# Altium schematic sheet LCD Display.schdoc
size 297 x 209 mm; Symbol: Drawing-Symbol_A4; @Project Name: Hưhwwuey; @Page Count: 4; @Update Date: 2026-10-18; @Create Date: 2026-10-18; @Schematic Name: Schematic1; @Page No: 4; @Page Name: P1; Company: EasyEDA.com; Version: V1.0; Page Size: A4; Device: Drawing-Symbol_A4; @Create Time: 08:51:09; @Update Time: 08:51:09; Border: 1; Width: 1170; Height: 825; Region Start: 1; X Region Count: 6; Y Region Count: 4; Blade Width: 10; Title Block Position: 3; @Board Name: Board1
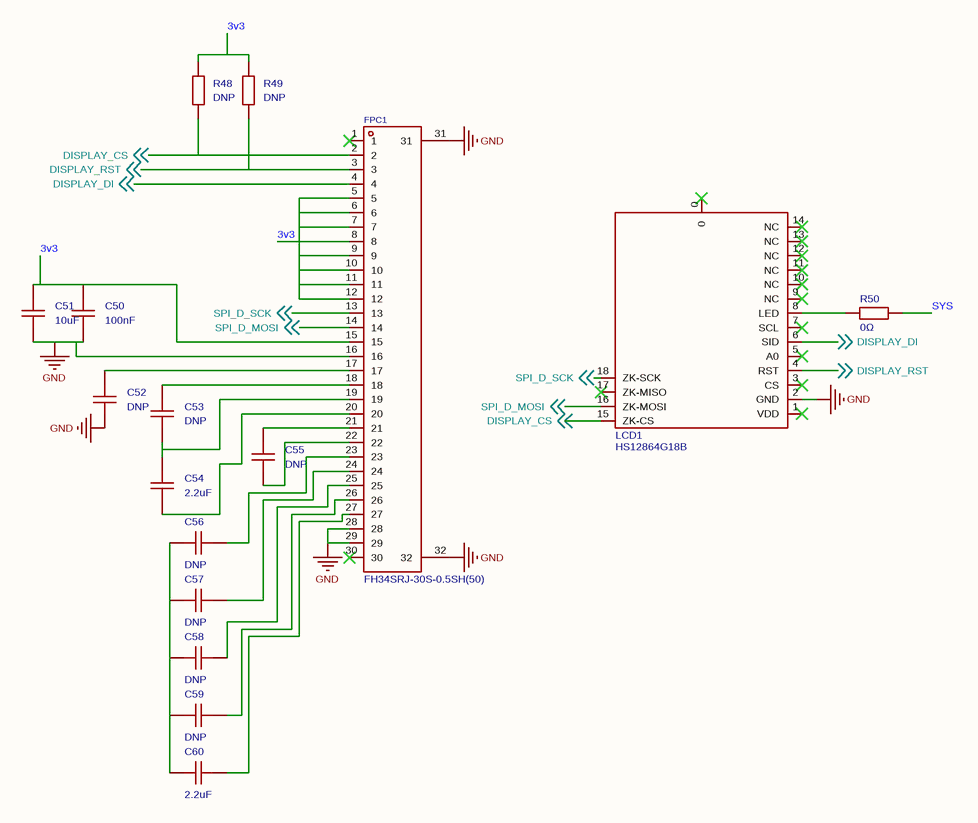
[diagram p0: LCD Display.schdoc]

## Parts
C50  100nF  [C0402]
C51  10uF  [C0603]
C52  DNP  [C0402]
C53  DNP  [C0402]
C54  2.2uF  [C0402]
C55  DNP  [C0402]
C56  DNP  [C0402]
C57  DNP  [C0402]
C58  DNP  [C0402]
C59  DNP  [C0402]
C60  2.2uF  [C0402]
FPC1  FH34SRJ-30S-0.5SH(50)  [FFC-SMD_30P-P0.50_FH34SRJ-30S-0.5SH]
LCD1  HS12864G18B  [COMM-TH_HS12864G18B]
R48  DNP  [R0402]
R49  DNP  [R0402]
R50  0Ω  [R0402]

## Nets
GND: C50.2 C51.1 C52.2 FPC1.16 FPC1.28 FPC1.29 FPC1.31 FPC1.32 LCD1.2(GND)
3v3: C50.1 C51.2 FPC1.5 FPC1.6 FPC1.7 FPC1.8 FPC1.9 FPC1.10 FPC1.11 FPC1.12 FPC1.15 R48.2 R49.2
DISPLAY_CS: FPC1.2 LCD1.15(ZK-CS) R48.1 ; off-sheet DISPLAY_CS
DISPLAY_DI: FPC1.4 LCD1.6(SID) ; off-sheet DISPLAY_DI
DISPLAY_RST: FPC1.3 LCD1.4(RST) R49.1 ; off-sheet DISPLAY_RST
SPI_D_MOSI: FPC1.14 LCD1.16(ZK-MOSI) ; off-sheet SPI_D_MOSI
SPI_D_SCK: FPC1.13 LCD1.18(ZK-SCK) ; off-sheet SPI_D_SCK
SYS: R50.1
NetC52_1: C52.1 FPC1.17
NetC53_1: C53.1 FPC1.18
NetC53_2: C53.2 C54.2 FPC1.19
NetC54_1: C54.1 FPC1.20
NetC55_1: C55.1 FPC1.21
NetC55_2: C55.2 FPC1.22
NetC56_1: C56.1 C57.1 C58.1 C59.1 C60.2
NetC56_2: C56.2 FPC1.23
NetC57_2: C57.2 FPC1.24
NetC58_2: C58.2 FPC1.25
NetC59_2: C59.2 FPC1.26
NetC60_1: C60.1 FPC1.27
NetLCD1_8: LCD1.8(LED) R50.2

Not connected (* = marked no-connect by the designer): FPC1 1* 30*; LCD1 0* 1(VDD)* 3(CS)* 5(A0)* 7(SCL)* 9(NC)* 10(NC)* 11(NC)* 12(NC)* 13(NC)* 14(NC)* 17(ZK-MISO)*

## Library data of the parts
C50 = CAP_0402: Symbol: CAP_OLD; 3D Model: b7d13df3e9464d7a99d0651d1a5b4d570819f05c4eef4c71ace90d822a990e87; 3D Model Transform: 39.37,19.685,0,0,0,0,0,0,0; ConvertToPcb: yes; ModelName: C0402_L1.0-W0.5-H0.5
C51 = CL10A106KP8NNNC: Capacitance:10uF Tolerance:±10% Tolerance:±10% Voltage Rating:10V Temperature Coefficient:X5R; Manufacturer: SAMSUNG(三星); AddInBom: yes; ModelId: 624118aa3cc7497086c383c2d72e08520819f05c4eef4c71ace90d822a990e87; ModelName: C0603_L1.6-W0.8-H0.8; ModelTransform: 62.992,31.496,0,0,0,0,0,0,0; Tolerance: ±10%; Voltage Rating: 10V; Temperature Coefficient: X5R
C52 = CAP_0402: Symbol: CAP_OLD; 3D Model: b7d13df3e9464d7a99d0651d1a5b4d570819f05c4eef4c71ace90d822a990e87; 3D Model Transform: 39.37,19.685,0,0,0,0,0,0,0; Add into BOM: no; ConvertToPcb: yes; ModelName: C0402_L1.0-W0.5-H0.5
C53 C55-C59 = CAP_0402: Symbol: CAP_OLD; Add into BOM: no; 3D Model: b7d13df3e9464d7a99d0651d1a5b4d570819f05c4eef4c71ace90d822a990e87; 3D Model Transform: 39.37,19.685,0,0,0,0,0,0,0; ConvertToPcb: yes; ModelName: C0402_L1.0-W0.5-H0.5
C54 C60 = CL05A225MQ5NSNC: Capacitance:2.2uF Tolerance:±20% Tolerance:±20% Voltage Rating:6.3V Temperature Coefficient:X5R; Manufacturer: SAMSUNG(三星); AddInBom: yes; ModelId: b7d13df3e9464d7a99d0651d1a5b4d570819f05c4eef4c71ace90d822a990e87; ModelName: C0402_L1.0-W0.5-H0.5; ModelTransform: 39.37,19.685,0,0,0,0,0,0,0; Tolerance: ±20%; Voltage Rating: 6.3V; Temperature Coefficient: X5R
FPC1 = FH34SRJ-30S-0.5SH(50): Locking Feature:Flip-top (front insert,rear flip) Contact Type:Double-Sided Contacts, Top and Bottom Entry Number of Contacts:30P Pitch:0.5mm Mounting Type:Surface Mount, Right Angle FFC, FCB Thickness:0.3mm FFC, FCB Thickness:0.3mm Height Above Board:1mm; Manufacturer: HRS(广濑); AddInBom: yes; ModelId: 0c4f2e658d844e86a41377a272355f670819f05c4eef4c71ace90d822a990e87; ModelTransform: 669.29,149.606,0,0,0,0,0.004,5.906,0; Number of Contacts: 30P; Pitch: 0.5mm; FFC, FCB Thickness: 0.3mm; Rated Voltage (Max): 50V; Current Rating (Max): 500mA; FPC/FFC Lock: Without buckle; Forward Foot / Back Foot: No polarity
LCD1 = HS12864G18B: Main Control Chip:ST7567 Size:3; Manufacturer: HS(汉昇); AddInBom: yes; ModelId: 82f3b8a5681848b091cb1c7b6c8d4e640819f05c4eef4c71ace90d822a990e87; ModelTransform: 3385.82,1968.5,0,0,0,0,-19.488,0,-185.039; Main Control Chip: ST7567
R48 = Res_0402: Symbol: Res; 3D Model: efdecb7dae4442949d28eecaf748420f0819f05c4eef4c71ace90d822a990e87; 3D Model Transform: 39.37,19.685,0,0,0,0,0,0,0; Add into BOM: no; ConvertToPcb: yes; ModelName: R0402_L1.0-W0.5-H0.4
R49 = Res_0402: Symbol: Res; Add into BOM: no; 3D Model: efdecb7dae4442949d28eecaf748420f0819f05c4eef4c71ace90d822a990e87; 3D Model Transform: 39.37,19.685,0,0,0,0,0,0,0; ConvertToPcb: yes; ModelName: R0402_L1.0-W0.5-H0.4
R50 = MR04X000PTL: Type:Thick Film Resistors Resistance: Power(Watts): Overload Voltage (Max): Temperature Coefficient:-200ppm/℃~+400ppm/℃ Temperature Coefficient:-200ppm/℃~+400ppm/℃ Operating Temperature Range:-55℃~+155℃ Operating Temperature Range:-55℃~+155℃; Manufacturer: Walsin(华新科); Symbol: MR04X000PTL_C396825; AddInBom: yes; ModelId: efdecb7dae4442949d28eecaf748420f0819f05c4eef4c71ace90d822a990e87; ModelName: R0402_L1.0-W0.5-H0.4; ModelTransform: 39.37,19.685,0,0,0,0,0,0,0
